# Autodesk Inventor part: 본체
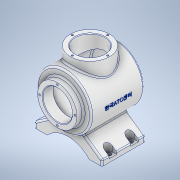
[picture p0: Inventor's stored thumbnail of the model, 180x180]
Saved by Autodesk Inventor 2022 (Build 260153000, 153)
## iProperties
Created: 2023-04
Part Number: 본체
Material: 알루미늄 6061
Document SubType Name: Modeling
Designer: Admin
Mass: 1291.94 g
Surface Area: 1063.05 cm^2
Volume: 478.495 cm^3
Density: 2.7 g/cm^3
Appearance: 알루미늄 - 평지
Author: Admin
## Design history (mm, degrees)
sketch "스케치2"
  geometry: L1 (-86.8, 0)-(86.8, 0) reference; L2 (0, -57.515)-(0, 99.419) reference; L3 (62, 0)-(62, 10); L4 (62, 10)-(23.355, 37.06); L5 (23.355, 37.06)-(23.355, 77); L6 (23.355, 77)-(-23.355, 77); L7 (-23.355, 77)-(-23.355, 37.06); L8 (-23.355, 37.06)-(-62, 10); L9 (-62, 10)-(-62, 0); L10 (-38.5, 0)-(38.5, 0); L11 (0, 0)-(0, 17); L12 (-62, 0)-(62, 0); A1 r 52.096 centre (0, -35.096) between (38.5, 0) and (-38.5, 0); 2 further points
  constraints: 20 end point, 4 symmetric about line, 3 perpendicular, 3 point on circle, 3 point on line, 1 centre point, 1 collinear, 1 horizontal, 1 midpoint, 1 parallel, 1 vertical
  dimensions: "d0" = 55 deg angle of L3 L4; "d1" = 10 distance of L3.start L3.end; "d2" = 124 distance between parallel lines of L3 L9; "d3" = 77 distance of L10.start L10.end; "d4" = 17 distance of L11.start L11.end; "d5" = 77 distance between parallel lines of L10 L6
extrude "돌출1" new body sketch "스케치2" stored distance "d6" = 80; taper "d7" = 0 deg
sketch "스케치3"
  geometry: L1 (77, 72.343)-(77, -93.292); L2 (0, -40)-(0, 40) reference; L3 (77, 48)-(127, 48); L4 (127, 48)-(127, -60); L5 (127, -60)-(77, -60); L6 (77, 48)-(77, -60); L7 (77, 40)-(37.06, 40) reference; L8 (-25.534, 0)-(153.205, 0) reference; L9 (77, 48)-(113, 48); L10 (113, 48)-(113, 60); L11 (113, 60)-(77, 60); L12 (77, 60)-(77, 48); L13 (0, 40)-(10, 40) reference; A1 r 113 centre (77, 53) between (77, -60) and (127, -48.336); 2 further points
  constraints: 18 end point, 4 point on line, 3 perpendicular, 2 horizontal, 2 parallel, 2 point on circle, 1 centre point, 1 collinear, 1 tangent, 1 vertical
  dimensions: "d8" = 77 distance between parallel lines of L2 L1; "d10" = 108 distance between parallel lines of L3 L5; "d12" = 226 diameter of A1; "d13" = 100 diameter of L4 L1; "d19" = 120 distance between parallel lines of L5 L11; "d20" = 72 diameter of L10 L1; "d21" = 20 distance between parallel lines of L13 L11
revolve "회전1" sketch "스케치3" stored, may be unused: angle "d14" = 360 deg
sketch "스케치6"
  geometry: L1 (77, 94.531)-(77, -106.028); L2 (0, -40)-(0, 40) reference; L3 (77, -53)-(120, -53); L4 (120, -53)-(120, 41); L5 (120, 41)-(77, 41); L6 (77, 41)-(77, -53); L7 (41, 60)-(113, 60) reference; L8 (77, 41)-(104, 41); L9 (104, 41)-(104, 60); L10 (104, 60)-(77, 60); L11 (77, 60)-(77, 41); A1 r 113 centre (77, 60) between (77, -53) and (120, -44.499); 3 further points
  constraints: 18 end point, 4 parallel, 3 point on line, 2 horizontal, 2 perpendicular, 2 point on circle, 1 centre point, 1 tangent, 1 vertical
  dimensions: "d22" = 77 distance between parallel lines of L2 L1; "d23" = 19 distance between parallel lines of L7 L5; "d24" = 54 diameter of L9.end L1; "d25" = 86 diameter of L4.end L1; "d27" = 113 distance between parallel lines of L7 L3; "d28" = 226 diameter of A1
revolve "회전2" sketch "스케치6" stored, may be unused: angle "d29" = 90 deg
node "작업 평면1"
sketch "스케치7"
  geometry: L1 (0, -84)-(0, 84) reference; L2 (86.8, 0)-(-86.8, 0) reference; C1 r 36 at (0, 0); 1 further point
  constraints: 1 centre point, 1 coincident
  dimensions: "d31" = 72 diameter of C1
extrude "돌출3" join sketch "스케치7" stored distance "d32" = 12; taper "d33" = 0 deg
sketch "스케치8"
  geometry: L1 (0, 84)-(0, -84) reference; L2 (-86.8, 0)-(86.8, 0) reference; C1 r 27 at (0, 0); 1 further point
  constraints: 1 centre point, 1 coincident
  dimensions: "d34" = 54 diameter of C1
extrude "돌출4" cut sketch "스케치8" distance "d35" = 40; taper "d36" = 0 deg
sketch "스케치9"
  geometry: A1 r 32.5 centre (0, 0) between (0, 32.5) and (32.5, 0); 3 further points
  constraints: 4 point on circle, 1 centre point
  dimensions: "d37" = 65 diameter of A1
hole "구멍1" sketch "스케치9" at (0, 32.5), (32.5, 0), (0, -32.5), (-32.5, 0) diameter "d38" = 3.45873; stored, may be unused: countersink angle "d42" = 90 deg, drill point angle "d44" = 118 deg; dims "d39" = 8, "d40" = 4, "d41" = 2, "d43" = 10
sketch "스케치10"
  geometry: A1 r 32.5 centre (0, 0) between (-32.5, 0) and (0, 32.5); 3 further points
  constraints: 4 point on circle, 1 centre point, 1 coincident
  dimensions: "d45" = 65 diameter of A1
hole "구멍2" sketch "스케치10" at (-32.5, 0), (0, 32.5), (32.5, 0), (0, -32.5) diameter "d46" = 3.45873; stored, may be unused: countersink angle "d50" = 90 deg, drill point angle "d52" = 118 deg; dims "d47" = 8, "d48" = 4, "d49" = 2, "d51" = 10
node "작업 평면2"
sketch "스케치11"
  geometry: L1 (86.8, 0)-(-86.8, 0) reference; L2 (0, -84)-(0, 84) reference; L3 (-62, -40)-(-62, 40) reference; L4 (-62, 27)-(-54, 27); L5 (-54, 27)-(-54, 13); L6 (-54, 13)-(-62, 13); L7 (-62, 13)-(-62, 27); L8 (-62, -13)-(-54, -13); L9 (-54, -13)-(-54, -27); L10 (-54, -27)-(-62, -27); L11 (-62, -27)-(-62, -13); L12 (-62, -40)-(-38.5, -40) reference; 7 further points
  constraints: 16 end point, 4 parallel, 2 horizontal, 2 midpoint, 2 perpendicular, 2 point on line, 2 symmetric about line, 6 other
  dimensions: "d54" = 14 distance of L8.end L9.end; "d55" = 8 distance from line of L3 point (-54, -20); "d56" = 20 distance from line of L12 point (-54, -20)
extrude "돌출5" cut sketch "스케치11" distance "d57" = 20; taper "d58" = 0 deg
sketch "스케치14"
  geometry: L1 (-38.5, -124)-(-38.5, 44) reference; L2 (-125.3, -40)-(48.3, -40) reference; 5 further points
  constraints: 3 symmetric about line
  dimensions: "d59" = 108 distance of point (-92.5, -60) point (15.5, -60); "d60" = 40 distance of point (-92.5, -20) point (-92.5, -60)
hole "구멍3" sketch "스케치14" at (15.5, -60), (-92.5, -60), (15.5, -20), (-92.5, -20) diameter "d61" = 9; stored, may be unused: countersink angle "d65" = 90 deg, drill point angle "d67" = 0 deg; dims "d62" = 8, "d63" = 4, "d64" = 2, "d66" = 20
node "작업 평면3"
sketch "스케치15"
  geometry: L1 (41, 60)-(113, 60) reference; L2 (0, -40)-(0, 40) reference; 2 further points
  constraints: 1 other
  dimensions: "d69" = 62 distance from line of L1 point (77, -2); "d70" = 77 distance from line of L2 point (77, -2)
feature "엠보싱1" sketch "스케치15" dims "d0" = 55 deg, "d1" = 10, "d2" = 124, "d3" = 77, "d4" = 17, "d5" = 77, "d71" = 0.5, "d72" = 0
fillet "모깎기1" dims "d73" = 3
chamfer "모따기1" distance "d74" = 1; stored, may be unused: second distance "d75" = 2, angle "d76" = 45 deg
fillet "모깎기2" dims "d77" = 3
fillet "모깎기3" dims "d78" = 3
fillet "모깎기4" dims "d79" = 3
node "솔리드1"
mirror "미러1"
feature "A9D066F2-1C7D-4E18-AEED-F7BC21143FA4" dims "d61" = 9, "d62" = 8, "d63" = 4, "d64" = 2, "d65" = 90 deg, "d66" = 20, "d67" = 0
other parameters: "d30" = 142, "d53" = 6, "d68" = 69.75
